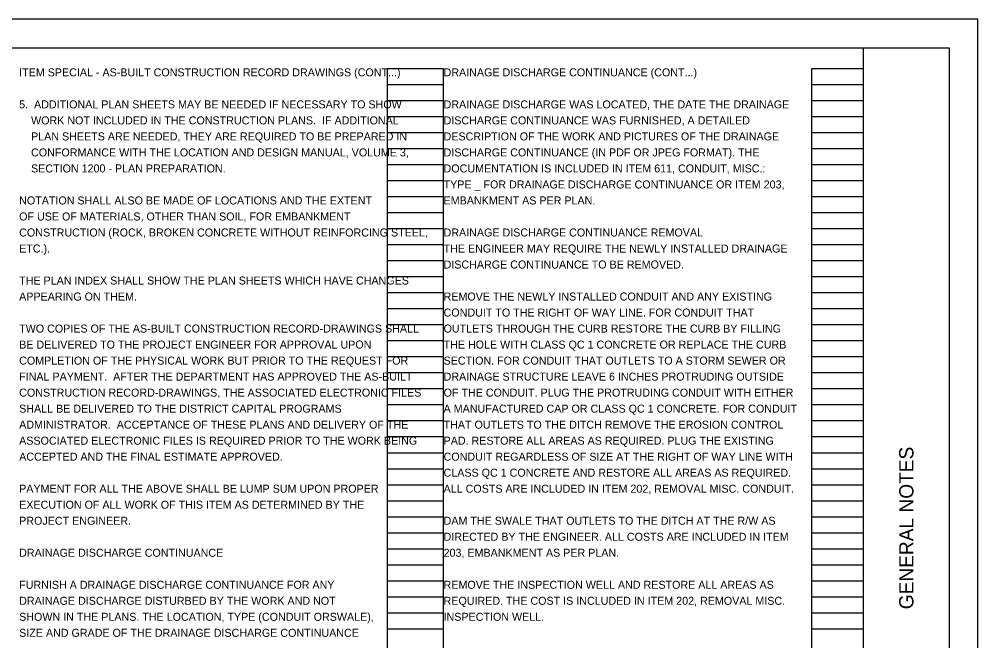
# Model space of a CAD drawing. Extents: x 0 to 34, y 0 to 22.
# Drawn here: x 17.24 to 34, y 11.13 to 22 of the extents above; entities that cross this region are included whole.
import ezdxf

# ---------------------------------------------------------------- set-up
doc = ezdxf.new("R2010")
doc.units = 0
for name, color, linetype in [('SH_Border', 7, 'Continuous'), ('SH_Cut_Line', 7, 'Continuous'), ('SH_Data', 7, 'Continuous'), ('SH_Text', 7, 'Continuous')]:
    doc.layers.add(name, color=color, linetype=linetype)

msp = doc.modelspace()

# ---------------------------------------------------------------- linework, layer by layer
at = {"layer": 'SH_Border'}
msp.add_line((32, 0.5), (32, 21.5), dxfattribs=at)
msp.add_lwpolyline([(1.5, 21.5), (33.5, 21.5), (33.5, 0.5), (1.5, 0.5)], close=True, dxfattribs=at)
at = {"layer": 'SH_Cut_Line'}
msp.add_lwpolyline([(0, 0), (34, 0), (34, 22), (0, 22)], close=True, dxfattribs=at)
at = {"layer": 'SH_Data'}
for p, q in [((23.68, 0.98), (23.68, 21.14)), ((23.68, 21.14), (24.66, 21.14)), ((24.66, 0.98), (24.66, 21.14)), ((31.1, 0.98), (31.1, 21.14)), ((31.1, 21.14), (32, 21.14)), ((32, 0.98), (32, 21.14)), ((23.68, 20.86), (24.66, 20.86)), ((31.1, 20.86), (32, 20.86)), ((23.68, 20.58), (24.66, 20.58)), ((31.1, 20.58), (32, 20.58)), ((23.68, 20.3), (24.66, 20.3)), ((31.1, 20.3), (32, 20.3)), ((23.68, 20.02), (24.66, 20.02)), ((31.1, 20.02), (32, 20.02)), ((23.68, 19.74), (24.66, 19.74)), ((31.1, 19.74), (32, 19.74)), ((23.68, 19.46), (24.66, 19.46)), ((31.1, 19.46), (32, 19.46)), ((23.68, 19.18), (24.66, 19.18)), ((31.1, 19.18), (32, 19.18)), ((23.68, 18.9), (24.66, 18.9)), ((31.1, 18.9), (32, 18.9)), ((23.68, 18.62), (24.66, 18.62)), ((31.1, 18.62), (32, 18.62)), ((23.68, 18.34), (24.66, 18.34)), ((31.1, 18.34), (32, 18.34)), ((23.68, 18.06), (24.66, 18.06)), ((31.1, 18.06), (32, 18.06)), ((23.68, 17.78), (24.66, 17.78)), ((31.1, 17.78), (32, 17.78)), ((23.68, 17.5), (24.66, 17.5)), ((31.1, 17.5), (32, 17.5)), ((23.68, 17.22), (24.66, 17.22)), ((31.1, 17.22), (32, 17.22)), ((23.68, 16.94), (24.66, 16.94)), ((31.1, 16.94), (32, 16.94)), ((23.68, 16.66), (24.66, 16.66)), ((31.1, 16.66), (32, 16.66)), ((23.68, 16.38), (24.66, 16.38)), ((31.1, 16.38), (32, 16.38)), ((23.68, 16.1), (24.66, 16.1)), ((31.1, 16.1), (32, 16.1)), ((23.68, 15.82), (24.66, 15.82)), ((31.1, 15.82), (32, 15.82)), ((23.68, 15.54), (24.66, 15.54)), ((31.1, 15.54), (32, 15.54)), ((23.68, 15.26), (24.66, 15.26)), ((31.1, 15.26), (32, 15.26)), ((23.68, 14.98), (24.66, 14.98)), ((31.1, 14.98), (32, 14.98)), ((23.68, 14.7), (24.66, 14.7)), ((31.1, 14.7), (32, 14.7)), ((23.68, 14.42), (24.66, 14.42)), ((31.1, 14.42), (32, 14.42)), ((23.68, 14.14), (24.66, 14.14)), ((31.1, 14.14), (32, 14.14)), ((23.68, 13.86), (24.66, 13.86)), ((31.1, 13.86), (32, 13.86)), ((23.68, 13.58), (24.66, 13.58)), ((31.1, 13.58), (32, 13.58)), ((23.68, 13.3), (24.66, 13.3)), ((31.1, 13.3), (32, 13.3)), ((23.68, 13.02), (24.66, 13.02)), ((31.1, 13.02), (32, 13.02)), ((23.68, 12.74), (24.66, 12.74)), ((31.1, 12.74), (32, 12.74)), ((23.68, 12.46), (24.66, 12.46)), ((31.1, 12.46), (32, 12.46)), ((23.68, 12.18), (24.66, 12.18)), ((31.1, 12.18), (32, 12.18)), ((23.68, 11.9), (24.66, 11.9)), ((31.1, 11.9), (32, 11.9)), ((23.68, 11.62), (24.66, 11.62)), ((31.1, 11.62), (32, 11.62)), ((23.68, 11.34), (24.66, 11.34)), ((31.1, 11.34), (32, 11.34))]:
    msp.add_line(p, q, dxfattribs=at)

# ---------------------------------------------------------------- texts
msp.add_text('GENERAL NOTES', height=0.25, rotation=90, dxfattribs=at).set_placement((32.875, 11.682))
at = {"layer": 'SH_Text'}
for s, p in [('ITEM SPECIAL - AS-BUILT CONSTRUCTION RECORD DRAWINGS (CONT...)', (17.24, 21)), ('DRAINAGE DISCHARGE CONTINUANCE (CONT...)', (24.66, 21)), ('5.  ADDITIONAL PLAN SHEETS MAY BE NEEDED IF NECESSARY TO SHOW', (17.24, 20.44)), ('DRAINAGE DISCHARGE WAS LOCATED, THE DATE THE DRAINAGE', (24.66, 20.44)), ('    WORK NOT INCLUDED IN THE CONSTRUCTION PLANS.  IF ADDITIONAL', (17.24, 20.16)), ('DISCHARGE CONTINUANCE WAS FURNISHED, A DETAILED', (24.66, 20.16)), ('    PLAN SHEETS ARE NEEDED, THEY ARE REQUIRED TO BE PREPARED IN', (17.24, 19.88)), ('DESCRIPTION OF THE WORK AND PICTURES OF THE DRAINAGE', (24.66, 19.88)), ('    CONFORMANCE WITH THE LOCATION AND DESIGN MANUAL, VOLUME 3,', (17.24, 19.6)), ('DISCHARGE CONTINUANCE (IN PDF OR JPEG FORMAT). THE', (24.66, 19.6)), ('    SECTION 1200 - PLAN PREPARATION.', (17.24, 19.32)), ('DOCUMENTATION IS INCLUDED IN ITEM 611, CONDUIT, MISC.:', (24.66, 19.32)), ('TYPE _ FOR DRAINAGE DISCHARGE CONTINUANCE OR ITEM 203,', (24.66, 19.04)), ('NOTATION SHALL ALSO BE MADE OF LOCATIONS AND THE EXTENT', (17.24, 18.76)), ('EMBANKMENT AS PER PLAN.', (24.66, 18.76)), ('OF USE OF MATERIALS, OTHER THAN SOIL, FOR EMBANKMENT', (17.24, 18.48)), ('CONSTRUCTION (ROCK, BROKEN CONCRETE WITHOUT REINFORCING STEEL,', (17.24, 18.2)), ('DRAINAGE DISCHARGE CONTINUANCE REMOVAL', (24.66, 18.2)), ('ETC.).', (17.24, 17.92)), ('THE ENGINEER MAY REQUIRE THE NEWLY INSTALLED DRAINAGE', (24.66, 17.92)), ('DISCHARGE CONTINUANCE TO BE REMOVED.', (24.66, 17.64)), ('THE PLAN INDEX SHALL SHOW THE PLAN SHEETS WHICH HAVE CHANGES', (17.24, 17.36)), ('APPEARING ON THEM.', (17.24, 17.08)), ('REMOVE THE NEWLY INSTALLED CONDUIT AND ANY EXISTING', (24.66, 17.08)), ('CONDUIT TO THE RIGHT OF WAY LINE. FOR CONDUIT THAT', (24.66, 16.8)), ('TWO COPIES OF THE AS-BUILT CONSTRUCTION RECORD-DRAWINGS SHALL', (17.24, 16.52)), ('OUTLETS THROUGH THE CURB RESTORE THE CURB BY FILLING', (24.66, 16.52)), ('BE DELIVERED TO THE PROJECT ENGINEER FOR APPROVAL UPON', (17.24, 16.24)), ('THE HOLE WITH CLASS QC 1 CONCRETE OR REPLACE THE CURB', (24.66, 16.24)), ('COMPLETION OF THE PHYSICAL WORK BUT PRIOR TO THE REQUEST FOR', (17.24, 15.96)), ('SECTION. FOR CONDUIT THAT OUTLETS TO A STORM SEWER OR', (24.66, 15.96)), ('FINAL PAYMENT.  AFTER THE DEPARTMENT HAS APPROVED THE AS-BUILT', (17.24, 15.68)), ('DRAINAGE STRUCTURE LEAVE 6 INCHES PROTRUDING OUTSIDE', (24.66, 15.68)), ('CONSTRUCTION RECORD-DRAWINGS, THE ASSOCIATED ELECTRONIC FILES', (17.24, 15.4)), ('OF THE CONDUIT. PLUG THE PROTRUDING CONDUIT WITH EITHER', (24.66, 15.4)), ('SHALL BE DELIVERED TO THE DISTRICT CAPITAL PROGRAMS', (17.24, 15.12)), ('A MANUFACTURED CAP OR CLASS QC 1 CONCRETE. FOR CONDUIT', (24.66, 15.12)), ('ADMINISTRATOR.  ACCEPTANCE OF THESE PLANS AND DELIVERY OF THE', (17.24, 14.84)), ('THAT OUTLETS TO THE DITCH REMOVE THE EROSION CONTROL', (24.66, 14.84)), ('ASSOCIATED ELECTRONIC FILES IS REQUIRED PRIOR TO THE WORK BEING', (17.24, 14.56)), ('PAD. RESTORE ALL AREAS AS REQUIRED. PLUG THE EXISTING', (24.66, 14.56)), ('ACCEPTED AND THE FINAL ESTIMATE APPROVED.', (17.24, 14.28)), ('CONDUIT REGARDLESS OF SIZE AT THE RIGHT OF WAY LINE WITH', (24.66, 14.28)), ('CLASS QC 1 CONCRETE AND RESTORE ALL AREAS AS REQUIRED.', (24.66, 14)), ('PAYMENT FOR ALL THE ABOVE SHALL BE LUMP SUM UPON PROPER', (17.24, 13.72)), ('ALL COSTS ARE INCLUDED IN ITEM 202, REMOVAL MISC. CONDUIT.', (24.66, 13.72)), ('EXECUTION OF ALL WORK OF THIS ITEM AS DETERMINED BY THE', (17.24, 13.44)), ('PROJECT ENGINEER.', (17.24, 13.16)), ('DAM THE SWALE THAT OUTLETS TO THE DITCH AT THE R/W AS', (24.66, 13.16)), ('DIRECTED BY THE ENGINEER. ALL COSTS ARE INCLUDED IN ITEM', (24.66, 12.88)), ('DRAINAGE DISCHARGE CONTINUANCE', (17.24, 12.6)), ('203, EMBANKMENT AS PER PLAN.', (24.66, 12.6)), ('FURNISH A DRAINAGE DISCHARGE CONTINUANCE FOR ANY', (17.24, 12.04)), ('REMOVE THE INSPECTION WELL AND RESTORE ALL AREAS AS', (24.66, 12.04)), ('DRAINAGE DISCHARGE DISTURBED BY THE WORK AND NOT', (17.24, 11.76)), ('REQUIRED. THE COST IS INCLUDED IN ITEM 202, REMOVAL MISC.', (24.66, 11.76)), ('SHOWN IN THE PLANS. THE LOCATION, TYPE (CONDUIT ORSWALE),', (17.24, 11.48)), ('INSPECTION WELL.', (24.66, 11.48)), ('SIZE AND GRADE OF THE DRAINAGE DISCHARGE CONTINUANCE', (17.24, 11.2))]:
    msp.add_text(s, height=0.14, dxfattribs=at).set_placement(p)

doc.saveas('drawing.dxf')
